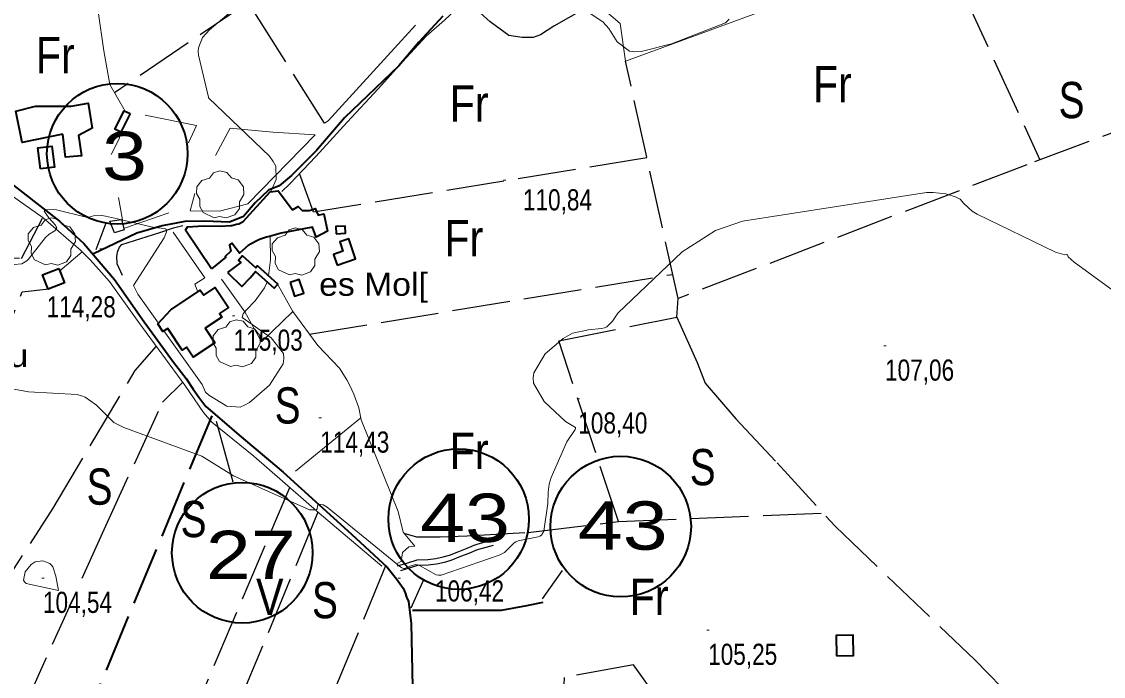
# Model space of a CAD drawing. Extents: x 483840 to 488445, y 4386047 to 4389027.
# Drawn here: x 486789.5 to 487237.6, y 4387028.7 to 4387299.7 of the extents above; entities that cross this region are included whole.
import ezdxf
from ezdxf.enums import TextEntityAlignment as Align

# ---------------------------------------------------------------- set-up
doc = ezdxf.new("R2010")
doc.units = 0
doc.header["$LTSCALE"] = 4
doc.linetypes.add('LONG_DASHED', pattern=[7.5, 6, -1.5])
doc.linetypes.add('MEDIUM_DASHED', pattern=[4.5, 3, -1.5])
for name, color, linetype, lineweight in [('13', 7, 'Continuous', 25), ('21', 7, 'Continuous', 25), ('25', 7, 'LONG_DASHED', 25), ('29', 7, 'Continuous', 13), ('36', 7, 'Continuous', 25), ('38', 7, 'Continuous', 25), ('47', 7, 'Continuous', 35), ('51', 7, 'Continuous', 13), ('6', 7, 'Continuous', 35), ('7', 7, 'Continuous', 13), ('9', 7, 'Continuous', 13)]:
    doc.layers.add(name, color=color, linetype=linetype, lineweight=lineweight)
doc.layers.add('31', color=7, linetype='Continuous')
doc.layers.add('5', color=7, linetype='Continuous')

msp = doc.modelspace()

# ---------------------------------------------------------------- linework, layer by layer
at = {"layer": '21'}
msp.add_lwpolyline([(486830.85, 4387217.8), (486831.98, 4387213.51), (486827.92, 4387212.36), (486826.11, 4387217.19)], close=True, dxfattribs=at)
at = {"layer": '25'}
for p, q in [((487167.1, 4387338.41), (487211.3, 4387242.53)), ((486908.77, 4387170.33), (487059.2, 4387195.11)), ((487036.68, 4387092.77), (487121.52, 4387096.27)), ((486940.29, 4387074.42), (486901.82, 4386981.23))]:
    msp.add_line(p, q, dxfattribs=at)
for points in [[(487027.25, 4387307.68), (487009.9, 4387297.92), (487004.45, 4387294.32), (487001.43, 4387293.17), (486996.78, 4387293.23), (486991.31, 4387293.99), (486983.52, 4387299.58), (486973.68, 4387308.72)], [(486915.01, 4387257.71), (486883.38, 4387307.69), (486827.98, 4387270.31)], [(487344.02, 4387291.9), (487205.83, 4387240.49), (487061.41, 4387185.08), (487039.63, 4387283.32)], [(487048.51, 4387243.3), (486910.35, 4387220.86), (486904.61, 4387236.84)], [(486734.71, 4387205.52), (486789.5, 4387201.73), (486798.21, 4387218.42)], [(486609.56, 4387156.72), (486630.57, 4387160.04), (486653.72, 4387157.46), (486670.08, 4387152.42), (486684.83, 4387149.81), (486683.34, 4387124.84), (486719.13, 4387119.6), (486726.62, 4387144.56), (486749.13, 4387138.98), (486759.81, 4387135.68), (486764.23, 4387135.46), (486768.88, 4387135.32), (486777.77, 4387158.23), (486789.75, 4387187.85), (486800.8, 4387189.1)], [(486947.85, 4387087.99), (486953.07, 4387086.46), (486962.83, 4387086.4), (486974.02, 4387086.91), (486999.32, 4387088.27), (487036.68, 4387092.77), (487012.01, 4387167.55), (487060.85, 4387177.44), (487061.41, 4387185.08)], [(487060.85, 4387177.44), (487069.29, 4387158.56), (487072.62, 4387150.03), (487085.39, 4387135.36), (487102.38, 4387117.11), (487126.54, 4387090.8), (487184.43, 4387035.35), (487221.11, 4386998.13)], [(486760.6, 4387033.34), (486802.57, 4387098.37), (486836.55, 4387155.29), (486845.33, 4387165.37)], [(486790.02, 4387014.6), (486823.68, 4387089.44), (486847.92, 4387142.22), (486856.25, 4387150.47)], [(486912.26, 4387096.64), (486871.83, 4386999.15), (486857.44, 4387005.51), (486900.59, 4387106.82)], [(487120.35, 4387019.61), (487056.35, 4387014.82), (487042.96, 4387033.47), (487014.29, 4387028.25), (487013.91, 4387022.11), (486955.59, 4387016.52)]]:
    msp.add_lwpolyline(points, dxfattribs=at)
at = {"layer": '29'}
for points in [[(486869.2, 4387218.53), (486864.66, 4387220.65), (486863.25, 4387223.19), (486863.35, 4387226.17), (486861.98, 4387228.58), (486862.02, 4387231.33), (486864.18, 4387233.93), (486867.37, 4387234.93), (486869.02, 4387237.12), (486871.59, 4387237.95), (486874.45, 4387237.3), (486876.4, 4387235.03), (486879.21, 4387234.21), (486881.34, 4387231.36), (486881.58, 4387228.23), (486879.7, 4387225.08), (486879.7, 4387222.4), (486877.88, 4387219.79), (486874.26, 4387218.45), (486871.49, 4387219.08)], [(486799.44, 4387199.04), (486794.9, 4387201.16), (486793.49, 4387203.7), (486793.59, 4387206.68), (486792.22, 4387209.09), (486792.26, 4387211.84), (486794.42, 4387214.44), (486797.61, 4387215.44), (486799.26, 4387217.63), (486801.83, 4387218.46), (486804.69, 4387217.81), (486806.64, 4387215.54), (486809.45, 4387214.72), (486811.58, 4387211.87), (486811.82, 4387208.74), (486809.94, 4387205.59), (486809.94, 4387202.91), (486808.12, 4387200.3), (486804.5, 4387198.96), (486801.73, 4387199.59)], [(486900.46, 4387194.89), (486895.92, 4387197.01), (486894.51, 4387199.55), (486894.61, 4387202.53), (486893.24, 4387204.94), (486893.28, 4387207.69), (486895.44, 4387210.29), (486898.63, 4387211.29), (486900.28, 4387213.48), (486902.85, 4387214.31), (486905.71, 4387213.66), (486907.66, 4387211.39), (486910.47, 4387210.57), (486912.6, 4387207.72), (486912.84, 4387204.59), (486910.96, 4387201.44), (486910.96, 4387198.76), (486909.14, 4387196.15), (486905.52, 4387194.81), (486902.75, 4387195.44)], [(486875.98, 4387156.9), (486871.44, 4387159.02), (486870.03, 4387161.56), (486870.13, 4387164.54), (486868.76, 4387166.95), (486868.8, 4387169.7), (486870.96, 4387172.3), (486874.15, 4387173.3), (486875.8, 4387175.49), (486878.37, 4387176.32), (486881.23, 4387175.67), (486883.18, 4387173.4), (486885.99, 4387172.58), (486888.12, 4387169.73), (486888.36, 4387166.6), (486886.48, 4387163.45), (486886.48, 4387160.77), (486884.66, 4387158.16), (486881.04, 4387156.82), (486878.27, 4387157.45)]]:
    msp.add_lwpolyline(points, close=True, dxfattribs=at)
at = {"layer": '36'}
msp.add_lwpolyline([(486831.23, 4387194.68), (486829.01, 4387199.52), (486828.98, 4387202.67), (486829.06, 4387203.27), (486829.15, 4387204.32), (486829.31, 4387204.69), (486830.01, 4387206.33), (486831, 4387207.52), (486846.75, 4387212.47), (486852.48, 4387214.41), (486856.32, 4387215.33)], dxfattribs=at)
at = {"layer": '38'}
msp.add_lwpolyline([(486945.14, 4387074.41), (486949.5, 4387075.72), (486953.29, 4387076.93), (486957.69, 4387077.02), (486961.02, 4387077.49), (486964.1, 4387078.1), (486966.69, 4387078.84), (486970.62, 4387080.42), (486974.01, 4387081.79), (486976.9, 4387082.96), (486978.18, 4387083.42), (486984.42, 4387085.15)], dxfattribs=at)
at = {"layer": '38', "linetype": 'MEDIUM_DASHED'}
msp.add_lwpolyline([(486946.61, 4387072.57), (486950.14, 4387073.63), (486953.66, 4387074.75), (486957.87, 4387074.84), (486961.39, 4387075.33), (486964.62, 4387075.97), (486967.4, 4387076.77), (486971.44, 4387078.38), (486974.83, 4387079.75), (486977.69, 4387080.91), (486978.85, 4387081.33), (486985, 4387083.03)], dxfattribs=at)
at = {"layer": '47'}
for points in [[(486806.59, 4387253.19), (486789.73, 4387249.68), (486787.14, 4387262.62), (486795.2, 4387264.76), (486809.98, 4387264.77), (486817.05, 4387266.02), (486818.71, 4387255.57), (486813.04, 4387252.65), (486814.34, 4387244.15), (486807.73, 4387243.57)], [(486834.4, 4387261.64), (486830.63, 4387253.99), (486828.15, 4387255.21), (486831.92, 4387262.86)], [(486797.31, 4387238.84), (486796.27, 4387247.46), (486802.02, 4387248.15), (486803.06, 4387239.53)], [(486868.22, 4387197.45), (486857.35, 4387213.44), (486858.19, 4387214.78), (486864.88, 4387215.21), (486871.55, 4387215.12), (486876.13, 4387215.27), (486876.51, 4387215.34), (486878.54, 4387215.84), (486879.44, 4387216.05), (486881.26, 4387217), (486892.46, 4387229.22), (486895.77, 4387229.7), (486901.66, 4387221.81), (486904.08, 4387223.13), (486905.64, 4387221.53), (486908.56, 4387221.56), (486910.07, 4387221.92), (486911.05, 4387222.43), (486912.36, 4387219.63), (486914.7, 4387220.2), (486916.17, 4387213.05), (486911.56, 4387210.56), (486910.04, 4387214.71), (486896.95, 4387212.12), (486892.2, 4387210.84), (486891.52, 4387210.63), (486890.92, 4387210.56), (486887.98, 4387209.48), (486886.39, 4387208.75), (486883.29, 4387206.99), (486879.8, 4387203.89), (486876.55, 4387208.06), (486875.64, 4387207.33), (486876.21, 4387204.77), (486873.77, 4387202.48), (486874.07, 4387202.25)], [(486919.83, 4387211.95), (486923.66, 4387212.18), (486923.48, 4387215.12), (486919.65, 4387214.89)], [(486920.17, 4387198.96), (486927.86, 4387201.55), (486925.07, 4387209.82), (486921.31, 4387208.57), (486922.6, 4387204.66), (486918.63, 4387203.36)], [(486874.8, 4387195.93), (486880.65, 4387190.07), (486884.2, 4387193.62), (486884.1, 4387193.71), (486886.41, 4387196.28), (486894.11, 4387189.35), (486895.63, 4387191.04), (486887.19, 4387198.61), (486886.47, 4387197.82), (486881.06, 4387202.73), (486879.38, 4387200.88), (486880.32, 4387200.01)], [(486804.97, 4387197.53), (486807.29, 4387191.65), (486800.49, 4387188.97), (486798.17, 4387194.85)], [(486900.71, 4387191.74), (486902.59, 4387186.12), (486906.35, 4387187.38), (486904.47, 4387193)], [(486851.24, 4387180.36), (486863.52, 4387188.59), (486864.92, 4387186.48), (486869.68, 4387189.65), (486875.18, 4387181.39), (486871.42, 4387178.9), (486872.43, 4387177.36), (486865.55, 4387172.85), (486869.53, 4387166.76), (486860.55, 4387160.89), (486857.85, 4387165.01), (486855.95, 4387163.76), (486850.02, 4387172.75), (486847.96, 4387171.41), (486845.86, 4387174.63)], [(487127.05, 4387037.14), (487134.06, 4387037.25), (487133.93, 4387045.68), (487126.92, 4387045.57)]]:
    msp.add_lwpolyline(points, close=True, dxfattribs=at)
at = {"layer": '51'}
for p, q in [((486831.22, 4387217.72), (486829.6, 4387226.98)), ((486850.54, 4387220.52), (486832.13, 4387214.25)), ((486805.34, 4387196.6), (486814.61, 4387204.45)), ((486902.9, 4387113.65), (486930.03, 4387135.72))]:
    msp.add_line(p, q, dxfattribs=at)
for points in [[(487086.01, 4387320.47), (487094.32, 4387303.32), (487039.63, 4387283.32), (487037.46, 4387298.95), (487014.19, 4387318.82)], [(486978.36, 4387312.96), (486973.36, 4387308.43), (486964.62, 4387300.37), (486957.09, 4387293.65), (486947.26, 4387283.06), (486937.12, 4387271.88), (486924.39, 4387258.1), (486911.43, 4387243.88), (486900.54, 4387232.63), (486897.27, 4387229.38)], [(486832.35, 4387262.66), (486826.02, 4387273.7), (486823.52, 4387287.61), (486821.18, 4387303.86)], [(486952.58, 4387298.22), (486916.52, 4387258.67), (486915.01, 4387257.71)], [(486858.67, 4387249.51), (486861.87, 4387256.67), (486840.62, 4387260.95)], [(486826.65, 4387244.72), (486830.05, 4387251.5), (486830.39, 4387254.05)], [(486869.79, 4387244.25), (486875.88, 4387255.65), (486893.57, 4387253.97), (486911.04, 4387252.82), (486883.16, 4387224.33), (486871.41, 4387221.27), (486859.26, 4387221.37), (486861.24, 4387228.62)], [(486798.37, 4387218.56), (486777.64, 4387233.12), (486771.29, 4387230.89)], [(486938.64, 4387074.29), (486912.77, 4387096.19), (486885.64, 4387119.84), (486868.29, 4387133.97), (486864.82, 4387137.92), (486857.1, 4387149.29), (486838.11, 4387175.22), (486825.9, 4387192.13), (486818, 4387201.02), (486813.93, 4387205.13), (486807.93, 4387210.25), (486798.37, 4387218.56)], [(486852.23, 4387212.54), (486865.39, 4387193.67), (486861.23, 4387191.03), (486862.48, 4387187.89)], [(486872.36, 4387193.12), (486882, 4387179.55), (486888.87, 4387167.22), (486901.89, 4387179.79)], [(486895.4, 4387191.26), (486901.89, 4387179.79), (486912.19, 4387165.61), (486921.21, 4387156.33), (486924.14, 4387151.48), (486925.46, 4387149.06), (486927.06, 4387145.51), (486929.15, 4387139.85), (486930.21, 4387134.89), (486945.42, 4387096.92), (486947.55, 4387088.34), (486952.34, 4387082.64), (486949.86, 4387082.3), (486947.2, 4387079.94), (486946.7, 4387076.27), (486946.62, 4387076.2), (486944.62, 4387075.07)]]:
    msp.add_lwpolyline(points, dxfattribs=at)
at = {"layer": '6', "lineweight": 25}
for p, q in [((486824.45, 4387216.32), (486820.28, 4387205.2)), ((486877.16, 4387109.05), (486870.2, 4387134.26)), ((487013.4, 4387072.55), (487005.13, 4387060.82)), ((486955.95, 4387068.64), (486950.72, 4387056.91))]:
    msp.add_line(p, q, dxfattribs=at)
at = {"layer": '6'}
msp.add_line((486815.26, 4387207.87), (486827.96, 4387192.96), dxfattribs=at)
for points in [[(486963.98, 4387301.94), (486954.08, 4387291.21), (486945.75, 4387281.5), (486923.23, 4387259.91), (486911.64, 4387246.42), (486901.28, 4387235.99), (486896.18, 4387231.77)], [(486769.4, 4387244.7), (486771.63, 4387243.37), (486777.04, 4387239.11), (486782.02, 4387235.2), (486805.26, 4387217.13), (486815.26, 4387207.87)], [(486896.18, 4387231.77), (486891.75, 4387230.01), (486886.29, 4387224.76), (486881.42, 4387219.11), (486875.57, 4387216.78), (486865.44, 4387217.17), (486857.06, 4387216.97), (486847.71, 4387215.22), (486837.18, 4387212.11), (486819.25, 4387203.55)], [(486827.96, 4387192.96), (486840.26, 4387175.44), (486852.39, 4387158.74), (486857.7, 4387152), (486860.52, 4387147.59), (486862.96, 4387144.22), (486865.82, 4387140.44), (486870.56, 4387136.44), (486879.61, 4387128.5), (486897.89, 4387113.26), (486926.12, 4387087.48), (486940.93, 4387073.82), (486944.75, 4387069.02), (486947.51, 4387065.21), (486948.41, 4387063.27), (486948.98, 4387061.46), (486949.78, 4387059.74), (486950.89, 4387050.52), (486951.42, 4387024.29)], [(486951.44, 4387056.08), (486988.25, 4387056.08), (486998.77, 4387057.99), (487005.46, 4387059.42)]]:
    msp.add_lwpolyline(points, dxfattribs=at)
at = {"layer": '6', "linetype": 'LONG_DASHED'}
msp.add_lwpolyline([(486868.26, 4387136.57), (486811.84, 4387000.91), (486805.15, 4386983.72), (486795.59, 4386928.58), (486789.85, 4386894.19), (486777.42, 4386867.44), (486761.17, 4386837.83), (486742.05, 4386817.76), (486701.89, 4386767.13)], dxfattribs=at)
at = {"layer": '6'}
for centre in [(486829.11, 4387245.04), (486970.55, 4387093.78), (487037.66, 4387090.69), (486880.89, 4387079.85)]:
    msp.add_circle(centre, 29.1, dxfattribs=at)
at = {"layer": '7'}
for p, q in [((486989.05, 4387234.06), (486990.05, 4387234.06)), ((486821.92, 4387205.68), (486822.92, 4387205.68)), ((486876.81, 4387177.88), (486877.81, 4387177.88)), ((487146.62, 4387165.47), (487147.62, 4387165.47)), ((487019.57, 4387143.58), (487020.57, 4387143.58)), ((486912.67, 4387135.67), (486913.67, 4387135.67)), ((486797.83, 4387069.32), (486798.83, 4387069.32)), ((486945.43, 4387069.38), (486946.43, 4387069.38)), ((487073.35, 4387047.81), (487074.35, 4387047.81))]:
    msp.add_line(p, q, dxfattribs=at)
at = {"layer": '9'}
for points in [[(486892.71, 4387229.26), (486892.81, 4387229.73), (486894.94, 4387234.38), (486894.78, 4387239.89), (486893.7, 4387241.88), (486892.17, 4387244.08), (486867.08, 4387268.01), (486866.96, 4387268.21), (486866.92, 4387268.3), (486866.91, 4387268.44), (486862.7, 4387285.84), (486862.67, 4387287.47), (486862.78, 4387288.95), (486864.41, 4387293.14), (486867.34, 4387296.38), (486876.25, 4387303.98)], [(487024.83, 4387303.2), (487030.34, 4387299.45), (487032.79, 4387296.88), (487036.15, 4387291.37), (487041.23, 4387287.54), (487043.48, 4387287.28), (487046.11, 4387287.36), (487058.66, 4387290.56), (487081.04, 4387299.25), (487082.53, 4387300.74)], [(487248.4, 4387183.45), (487225.41, 4387200.09), (487223, 4387202.41), (487222.72, 4387203.14), (487222.58, 4387203.24), (487222.42, 4387203.29), (487221.61, 4387203.13), (487217.78, 4387204.25), (487185.29, 4387220.06), (487183.27, 4387221.3), (487179.72, 4387224.38), (487178.2, 4387226.2), (487177.46, 4387226.65), (487176.58, 4387227.07), (487172.25, 4387228.38), (487167.1, 4387229.04), (487164.34, 4387228.99), (487088.11, 4387217.06), (487076.97, 4387213.27), (487063.15, 4387204.43), (487036.44, 4387178.98), (487034.21, 4387175.74), (487031.87, 4387173.45), (487030.87, 4387173.02), (487029.73, 4387172.68), (487024.34, 4387172.18), (487017.72, 4387170.7), (487013.83, 4387168.54), (487006.42, 4387162.21), (487001.68, 4387154.38), (487001.4, 4387152.25), (487001.57, 4387150.12), (487005.93, 4387142.53), (487014.72, 4387134.22), (487018.87, 4387131.66), (487018.91, 4387131.32), (487018.83, 4387130.92), (487015.28, 4387125.82), (487008.79, 4387110.94), (487008.02, 4387108.29)], [(486779.88, 4387199.25), (486786.37, 4387199.13), (486789.64, 4387199.49), (486791.7, 4387200.76), (486792.39, 4387201.43), (486799.42, 4387210.31), (486800.93, 4387211.81), (486803.21, 4387213.18), (486804.05, 4387214.31), (486803.87, 4387214.84), (486803.52, 4387215.47), (486800.78, 4387218.55), (486798.89, 4387221.3), (486799.07, 4387221.72), (486799.57, 4387222.01), (486803.9, 4387221.81), (486816.22, 4387218.81), (486817.3, 4387218.8), (486819.31, 4387219.27), (486822.76, 4387219.41), (486824.2, 4387219.23), (486830.51, 4387217.76), (486830.52, 4387217.76)], [(486830.88, 4387217.67), (486844.36, 4387214.52), (486848.87, 4387214.12), (486849.12, 4387213.99), (486849.31, 4387213.81), (486849.56, 4387212.76), (486848.48, 4387210.18), (486835.82, 4387190.49), (486837.58, 4387186.94), (486846.13, 4387174.92)], [(486891.74, 4387194.53), (486892.61, 4387201.06), (486892.45, 4387210.91)], [(486848.42, 4387171.71), (486864.22, 4387149.51), (486865.66, 4387146.32), (486867.08, 4387145.07), (486874.46, 4387140.47), (486880.03, 4387140.18), (486881.88, 4387140.95), (486883.86, 4387142.08), (486892.14, 4387149.24), (486897.81, 4387158.05), (486898.15, 4387160.22), (486897.96, 4387162.28), (486892.81, 4387168.77), (486880.91, 4387177.23), (486881.31, 4387178.83), (486882.47, 4387180.33), (486886.24, 4387184.15), (486890.17, 4387189.51), (486890.94, 4387191.28), (486891.17, 4387191.99)], [(487008.02, 4387108.29), (487007.59, 4387104.9), (487007.41, 4387100.27), (487005.82, 4387088.8), (487004.81, 4387087.1), (487004.19, 4387086.73), (487003.41, 4387086.41), (486995.11, 4387084.73), (486994.22, 4387084.38), (486993.45, 4387083.98), (486989.55, 4387079.96), (486987.33, 4387078.8), (486963.23, 4387070.51), (486962.18, 4387070.54), (486961.14, 4387070.72), (486954.31, 4387074.55), (486953.51, 4387074.81), (486952.75, 4387074.94), (486950.36, 4387074.36), (486948.5, 4387073.41), (486948.08, 4387073.31), (486947.7, 4387073.27), (486946.66, 4387073.74), (486916.01, 4387098.75), (486914.44, 4387099.73), (486912.18, 4387099.91), (486911.92, 4387098.06), (486911.61, 4387097.76), (486911.18, 4387097.56), (486908.76, 4387097.59), (486877.31, 4387111.69), (486864.17, 4387119.82), (486831.89, 4387131.72), (486827.75, 4387133.75), (486820.52, 4387140.95), (486815.83, 4387144.27), (486814.24, 4387144.87), (486812.51, 4387145.34), (486792.42, 4387146.42), (486784.01, 4387147.93)]]:
    msp.add_lwpolyline(points, dxfattribs=at)
msp.add_lwpolyline([(486804.76, 4387064.24), (486791.45, 4387067.13), (486790.73, 4387067.77), (486790.28, 4387068.5), (486790.91, 4387071.89), (486793.5, 4387075.02), (486794.29, 4387075.59), (486795.11, 4387076.04), (486798.31, 4387076.56), (486801.21, 4387075.4), (486801.83, 4387074.77), (486802.38, 4387074.02), (486803.71, 4387070.2)], close=True, dxfattribs=at)

# ---------------------------------------------------------------- texts
at = {"layer": '13', "width": 1.25}
for s, p in [('3', (486832.11, 4387234.13)), ('43', (486973.18, 4387084.32)), ('43', (487038.48, 4387081.12)), ('27', (486884.4, 4387068.96))]:
    msp.add_text(s, height=20, dxfattribs=at).set_placement(p, align=Align.CENTER)
at = {"layer": '31'}
for s, width, p in [('Fr', 0.85, (486803.47, 4387278.38)), ('Fr', 0.85, (487125.32, 4387266.38)), ('Fr', 0.85, (486974.89, 4387258.32)), ('S', 0.8, (487224.38, 4387259.76)), ('Fr', 0.85, (486972.69, 4387202.6)), ('S', 0.8, (486899.68, 4387133.34)), ('Fr', 0.85, (486974.89, 4387114.53)), ('S', 0.8, (487071.6, 4387107.81)), ('S', 0.8, (486821.78, 4387099.75)), ('S', 0.8, (486860.73, 4387086.31)), ('V', 0.85, (486892.3, 4387054.07)), ('S', 0.8, (486915.14, 4387052.72)), ('Fr', 0.85, (487049.45, 4387054.07))]:
    msp.add_text(s, height=15, dxfattribs=dict(at, width=width)).set_placement(p, align=Align.CENTER)
at = {"layer": '5'}
for s, width, p in [('es Mol[', 1.1, (486912.72, 4387186.24)), ('Son Pau', 1.15, (486736.22, 4387156.75))]:
    msp.add_text(s, height=9.5, dxfattribs=dict(at, width=width)).set_placement(p)
at = {"layer": '7', "width": 0.8}
for s, p in [('110,84', (486997.14, 4387221.59)), ('114,28', (486799.88, 4387177.31)), ('115,03', (486877.31, 4387163.51)), ('107,06', (487147.12, 4387151.1)), ('108,40', (487020.07, 4387129.21)), ('114,43', (486913.17, 4387121.3)), ('106,42', (486960.7, 4387059.67)), ('104,54', (486798.33, 4387054.95)), ('105,25', (487073.85, 4387033.44))]:
    msp.add_text(s, height=8.75, dxfattribs=at).set_placement(p)

doc.saveas('drawing.dxf')
